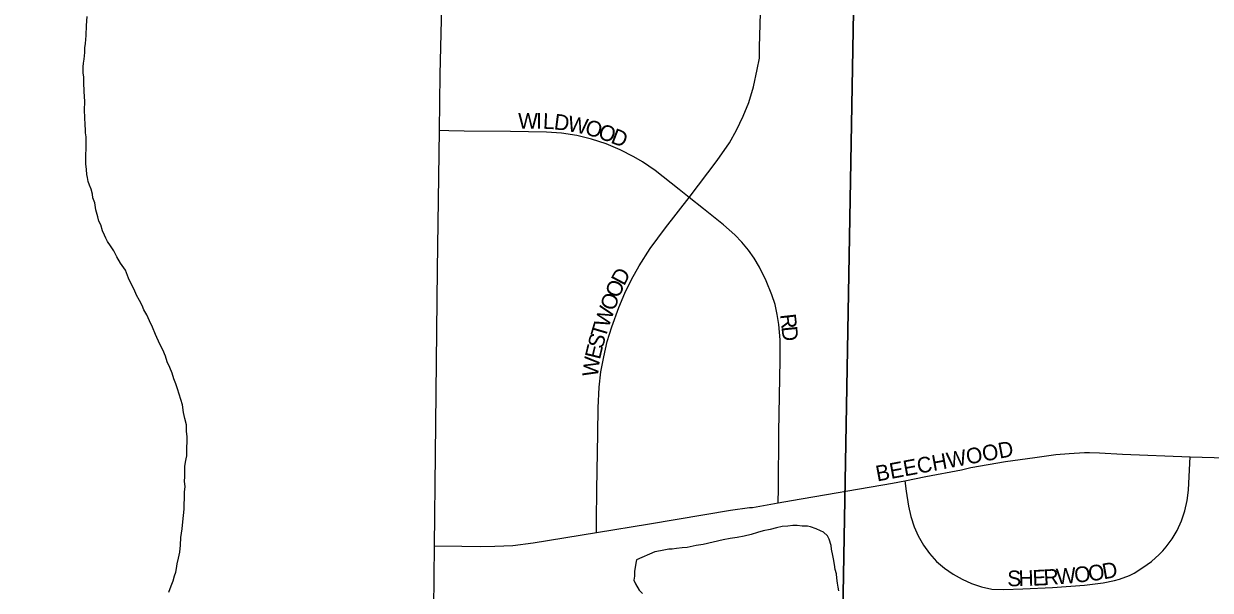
# Model space of a CAD drawing. Extents: x 1587405 to 1714697, y 1028970 to 1155083.
# Drawn here: x 1669662 to 1673451, y 1113302 to 1115110 of the extents above; entities that cross this region are included whole.
import ezdxf

# ---------------------------------------------------------------- set-up
doc = ezdxf.new("R2010")
doc.units = 0
for name, color, linetype in [('GM_X_Minor_Lake', 7, 'Continuous'), ('GM_X_Minor_River', 7, 'Continuous'), ('GM_X_Section', 7, 'Continuous'), ('GM_X_Township_Road', 7, 'Continuous'), ('GM_X_Township_Subdivision', 7, 'Continuous'), ('GM_X_Township_Subdivision_Text', 7, 'Continuous')]:
    doc.layers.add(name, color=color, linetype=linetype)

msp = doc.modelspace()

# ---------------------------------------------------------------- linework, layer by layer
at = {"layer": 'GM_X_Minor_Lake'}
for points in [[(1672264.5, 1113299.8), (1672262.6, 1113311.9), (1672260.7, 1113324), (1672258.9, 1113340.1), (1672257.1, 1113354.1), (1672253.2, 1113368.2), (1672251.4, 1113384.3), (1672247.6, 1113402.5), (1672245.7, 1113412.5), (1672242, 1113432.7), (1672240.1, 1113444.8), (1672234.3, 1113464.9), (1672228.4, 1113475.1), (1672216.5, 1113487.2), (1672206.5, 1113491.4), (1672192.4, 1113497.6), (1672174.4, 1113503.9), (1672164.4, 1113506), (1672148.2, 1113506.2), (1672132.2, 1113508.4), (1672118.1, 1113508.6), (1672101.9, 1113506.8), (1672083.8, 1113505.1), (1672065.6, 1113501.3), (1672045.4, 1113495.5), (1672023.2, 1113491.8), (1672005, 1113486), (1671984.7, 1113480.3), (1671962.5, 1113474.5), (1671940.3, 1113470.8), (1671918.1, 1113467.1), (1671895.9, 1113463.3), (1671831.3, 1113448.1), (1671809, 1113444.4), (1671780.8, 1113438.8), (1671764.6, 1113436.9)], [(1671764.6, 1113436.9), (1671746.5, 1113435.2), (1671732.4, 1113433.4), (1671722.3, 1113433.5), (1671706.1, 1113429.7), (1671696, 1113427.8), (1671677.8, 1113424), (1671619.1, 1113398.7)], [(1671619.1, 1113398.7), (1671617, 1113388.7), (1671614.8, 1113374.6), (1671612.6, 1113362.6), (1671612.4, 1113346.6), (1671610.2, 1113334.5), (1671616.1, 1113322.4), (1671627.9, 1113302.1), (1671637.9, 1113292)]]:
    msp.add_lwpolyline(points, dxfattribs=at)
at = {"layer": 'GM_X_Minor_River'}
for points in [[(1670114.7, 1114049.2), (1670106.9, 1114069.4), (1670097, 1114087.6), (1670083.3, 1114117.9), (1670073.6, 1114142.2), (1670063.7, 1114162.4), (1670055.9, 1114180.6), (1670046.1, 1114196.8), (1670040.2, 1114210.9), (1670032.3, 1114227.1), (1670022.5, 1114243.3), (1670014.7, 1114261.5), (1670004.8, 1114281.7), (1669997, 1114297.9), (1669987.3, 1114324.1), (1669971.4, 1114346.4), (1669959.6, 1114366.7), (1669949.8, 1114384.9), (1669939.9, 1114401.1), (1669930, 1114415.3), (1669924.1, 1114425.4), (1669920.2, 1114435.5), (1669914.3, 1114449.6), (1669908.5, 1114467.8), (1669902.6, 1114479.9), (1669898.8, 1114494), (1669893, 1114516.2), (1669889.3, 1114538.3), (1669883.4, 1114554.5), (1669881.6, 1114566.6), (1669877.8, 1114582.7), (1669871.9, 1114594.8), (1669868, 1114606.9), (1669866.1, 1114619), (1669864.3, 1114629.1), (1669862.4, 1114645.1), (1669860.7, 1114663.2), (1669861, 1114689.4), (1669861.3, 1114713.4), (1669861.6, 1114733.5), (1669861.8, 1114749.6), (1669859.9, 1114761.7), (1669860, 1114771.7), (1669858.2, 1114787.8), (1669856.8, 1114834), (1669857.2, 1114862.2), (1669855.6, 1114894.3), (1669853.9, 1114922.5), (1669854.1, 1114940.5), (1669852.3, 1114952.6), (1669852.4, 1114962.7), (1669852.5, 1114972.7), (1669852.7, 1114984.8), (1669854.9, 1114996.8), (1669857.2, 1115018.8), (1669857.4, 1115032.9), (1669859.5, 1115046.9), (1669861.9, 1115073), (1669862.3, 1115105.1), (1669864.7, 1115133.2)], [(1670125.2, 1113295.8), (1670133.5, 1113315.8), (1670139.7, 1113331.8), (1670144, 1113347.8), (1670148.2, 1113359.8), (1670150.3, 1113371.8), (1670152.5, 1113385.8), (1670156.8, 1113403.9), (1670161.1, 1113423.9), (1670163.4, 1113446), (1670163.7, 1113470.1), (1670168.1, 1113498.1), (1670170.3, 1113520.2), (1670172.6, 1113540.3), (1670174.9, 1113560.3), (1670175.1, 1113576.4), (1670175.3, 1113594.5), (1670175.6, 1113614.5), (1670177.8, 1113632.6), (1670176, 1113648.7), (1670176.2, 1113664.8), (1670176.4, 1113680.8), (1670176.6, 1113696.9), (1670178.8, 1113710.9), (1670181, 1113720.9), (1670183.1, 1113730.9), (1670183.3, 1113745), (1670183.5, 1113759.1), (1670183.7, 1113775.1), (1670183.9, 1113791.2), (1670182.1, 1113809.3), (1670182.4, 1113829.4), (1670176.6, 1113849.6), (1670172.8, 1113869.7), (1670169.1, 1113893.8), (1670153.6, 1113944.3), (1670147.8, 1113960.4), (1670141.9, 1113976.6), (1670136.1, 1113994.7), (1670128.3, 1114012.9), (1670120.5, 1114031.1), (1670114.7, 1114049.2)]]:
    msp.add_lwpolyline(points, dxfattribs=at)
at = {"layer": 'GM_X_Section'}
for points in [[(1667042.5, 1118475.3), (1672368.2, 1118326.9), (1672274.3, 1113050.6), (1666972.8, 1113204.7)], [(1672368.2, 1118326.9), (1677623.6, 1118159.2), (1677539.9, 1112896.8), (1672274.3, 1113050.6)]]:
    msp.add_lwpolyline(points, close=True, dxfattribs=at)
at = {"layer": 'GM_X_Township_Road'}
for points in [[(1670989.6, 1114769), (1670992.1, 1114948.7), (1670998.4, 1115210.9), (1671000.6, 1115538.5), (1671000.8, 1115568.2)], [(1670973.8, 1113443.4), (1670977.4, 1113735.7), (1670983.4, 1114325.6), (1670989.6, 1114769)], [(1670966.9, 1113012.7), (1670971.3, 1113244.1), (1670973.8, 1113443.4)]]:
    msp.add_lwpolyline(points, dxfattribs=at)
at = {"layer": 'GM_X_Township_Subdivision'}
for points in [[(1671786.9, 1114555.6), (1671876.5, 1114674.1), (1671916, 1114729.8), (1671938.5, 1114770), (1671959.6, 1114815.2), (1671978, 1114858.9), (1671992.6, 1114908.8), (1672004.7, 1114963.9), (1672011.1, 1114999.9), (1672012, 1115035.8), (1672016, 1115180.7), (1672016.6, 1115234), (1672017.4, 1115381.3), (1672020.3, 1115561.1), (1672020.1, 1115659.1), (1672020, 1115715.2)], [(1671786.9, 1114555.6), (1671755.1, 1114580.6), (1671678.4, 1114641.7), (1671638.3, 1114669.3), (1671610.3, 1114685.7), (1671566.6, 1114707.6), (1671521.7, 1114726.9), (1671475.5, 1114742.3), (1671428.1, 1114753.4), (1671379.9, 1114760.6), (1671331.2, 1114764.4), (1671216.7, 1114766.1), (1671069, 1114766.8), (1671019.8, 1114768.1), (1670989.6, 1114769)], [(1671491.1, 1113486.6), (1671491.4, 1113524.2), (1671492.3, 1113622.5), (1671495.2, 1113802.3), (1671496, 1113884.2), (1671499.6, 1113949.8), (1671505.4, 1113998.8), (1671514.1, 1114047.4), (1671525.6, 1114095.4), (1671539.8, 1114142.6), (1671562.2, 1114204.4), (1671581.2, 1114249.9), (1671602.7, 1114294.3), (1671627, 1114337.3), (1671662.8, 1114392.4), (1671711.1, 1114458.7), (1671786.9, 1114555.6)], [(1672071.6, 1113581.1), (1672072, 1113626.8), (1672073.6, 1113807.2), (1672078, 1114036.5), (1672077.2, 1114101.7), (1672073.2, 1114150.3), (1672068.4, 1114182.4), (1672061.2, 1114213.9), (1672051.2, 1114244.7), (1672032.7, 1114289.8), (1672011.1, 1114333.6), (1671994.7, 1114361.5), (1671976, 1114387.9), (1671955.3, 1114412.9), (1671932.9, 1114436.4), (1671896.5, 1114468.8), (1671832.6, 1114519.8), (1671786.9, 1114555.6)], [(1672475.3, 1113650.7), (1672543.1, 1113665.3), (1672656.1, 1113686.5), (1672686.1, 1113693.3), (1672797.5, 1113713.4), (1672891, 1113725.5), (1672957.4, 1113735.3), (1673000.1, 1113738.9), (1673049.5, 1113741.6), (1673065.6, 1113741.5), (1673097.5, 1113740.6), (1673170.4, 1113736.1), (1673386.5, 1113727.4)], [(1672475.3, 1113650.7), (1672480.3, 1113618.7), (1672487.9, 1113570), (1672494.7, 1113537.4), (1672505.7, 1113504.1), (1672518.6, 1113475.2), (1672535.3, 1113446.3), (1672554.9, 1113419.3), (1672577, 1113394.2), (1672589.1, 1113382.8), (1672602.2, 1113372.2), (1672629.5, 1113353.1), (1672658.4, 1113336.8), (1672688.7, 1113323.1), (1672720.4, 1113312.6), (1672753.1, 1113305.7), (1672791.4, 1113304), (1672852.3, 1113305.9), (1672947.2, 1113310.5), (1673049, 1113318.3), (1673109.3, 1113325.4), (1673145.3, 1113332.8), (1673161.4, 1113337.4), (1673192.5, 1113349.5), (1673207.4, 1113356.9), (1673236, 1113374.1), (1673262.9, 1113393.6), (1673288, 1113415.5), (1673299.5, 1113427.6), (1673310.5, 1113440.7), (1673329.2, 1113466.3), (1673344.8, 1113493), (1673359.2, 1113523.7), (1673369.9, 1113555.4), (1673376.9, 1113588), (1673380.9, 1113620.9), (1673384.4, 1113686.5), (1673386.5, 1113727.4)], [(1673386.5, 1113727.4), (1673576.9, 1113722.5), (1673606.9, 1113721.8)], [(1672071.6, 1113581.1), (1672113.7, 1113588.6), (1672436.1, 1113643.6), (1672475.3, 1113650.7)], [(1671491.1, 1113486.6), (1671660.9, 1113514.2), (1671918.7, 1113557.4), (1671979.4, 1113565.9), (1671989, 1113566.3), (1672071.6, 1113581.1)], [(1670973.8, 1113443.4), (1671060.9, 1113442.4), (1671121.9, 1113441.6), (1671167, 1113442.5), (1671224, 1113444.7), (1671288.7, 1113453.6), (1671491.1, 1113486.6)]]:
    msp.add_lwpolyline(points, dxfattribs=at)

# ---------------------------------------------------------------- texts
at = {"layer": 'GM_X_Township_Subdivision_Text'}
for s, rotation, p in [('W', 359.7478, (1671240.7, 1114775.5)), ('I', 359.7556, (1671297.9, 1114775.2)), ('L', 357.2945, (1671319.3, 1114775.2)), ('D', 352.7015, (1671353.4, 1114773.6)), ('W', 349.3463, (1671396.3, 1114768.1)), ('O', 344.8503, (1671451.5, 1114757.8)), ('O', 339.27, (1671492.7, 1114746.7)), ('D', 338.9656, (1671533.8, 1114731.1)), ('D', 61.7925, (1671579.2, 1114271.3)), ('O', 67.4356, (1671562.9, 1114231.8)), ('O', 69.7816, (1671547.9, 1114191)), ('W', 70.9749, (1671529.3, 1114137.2)), ('T', 73.5704, (1671519.6, 1114104)), ('R', 276.2544, (1672077.3, 1114181.9)), ('S', 74.3998, (1671510.1, 1114070.3)), ('D', 275.7585, (1672081.6, 1114142.7)), ('E', 76.4341, (1671502, 1114036.5)), ('W', 82.9209, (1671495.2, 1113981.2)), ('BEECHWOOD', 10.5828, (1672387.6, 1113648.9)), ('D', 10.2464, (1673110.5, 1113336.5)), ('S', 0.2186, (1672802.8, 1113314.7)), ('H', 1.7621, (1672839.5, 1113314.8)), ('E', 2.6285, (1672884.3, 1113316.2)), ('R', 3.4848, (1672920.2, 1113317.9)), ('W', 4.8962, (1672961.1, 1113320.4)), ('O', 6.0052, (1673019.2, 1113325.4)), ('O', 7.7025, (1673064.5, 1113330.1))]:
    msp.add_text(s, height=50, rotation=rotation, dxfattribs=at).set_placement(p)

doc.saveas('drawing.dxf')
